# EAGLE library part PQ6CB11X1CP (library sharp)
Compact SMD CMOS Step-up LED Driver 6 LEDs in series Source: http://document.sharpsma.com/files/PQ6CB11X1CP.pdf
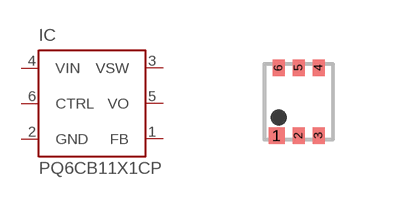
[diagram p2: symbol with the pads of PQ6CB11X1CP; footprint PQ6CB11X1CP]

Designator prefix IC

## PQ6CB11X1CP (OC_FARNELL: unknown; OC_NEWARK: unknown)  [PQ6CB11X1CP]
1  FB  in
2  GND  pwr
3  VSW  in
4  VIN  in
5  VO  out
6  CTRL  in

## Footprint PQ6CB11X1CP (pad centres in mm)
6-pin SMD 1.8 mm x 2.0 mm x 0.8 mm Source: http://document.sharpsma.com/files/PQ6CB11X1CP.pdf
smd 0.4 x 0.4: 1 -0.55,-0.85
smd 0.3 x 0.4: 2 0,-0.85; 3 0.5,-0.85; 4 0.5,0.85; 5 0,0.85; 6 -0.5,0.85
